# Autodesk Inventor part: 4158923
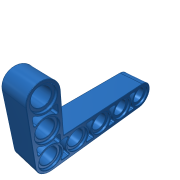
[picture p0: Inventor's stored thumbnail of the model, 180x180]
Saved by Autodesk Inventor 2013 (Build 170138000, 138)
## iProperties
Created: 2013-03
Part Number: 4158923
Material: Generic
Document SubType Name: Modeling
Designer: perblt
Density: 1 g/cm^3
Author: perblt
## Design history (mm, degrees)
sketch "Sketch1"
  geometry: L1 (-1, 2.182)-(1, 2.182); L2 (1, -2.182)-(-1, 2.182); L3 (-1, -2.182)-(1, 2.182); L4 (-2.182, -1)-(-2.182, 1); L5 (2.182, -1)-(-2.182, 1); L6 (-2.182, -1)-(2.182, 1); L7 (2.182, -1)-(1, -1); L8 (-1, -1)-(-2.182, -1); L9 (-1, -2.182)-(-1, -1); L10 (1, 2.182)-(1, 1); L11 (1, -1)-(1, -2.182); L12 (-2.182, 1)-(-1, 1); L13 (1, 1)-(2.182, 1); L14 (-1, 1)-(-1, 2.182); A1 r 2.4 centre (0, 0) between (2.182, -1) and (2.182, 1); A2 r 2.4 centre (0, 0) between (1, 2.182) and (-1, 2.182); A3 r 2.4 centre (0, 0) between (-2.182, 1) and (-2.182, -1); A4 r 2.4 centre (0, 0) between (-1, -2.182) and (1, -2.182); 1 further point
  constraints: 28 end point, 8 parallel, 8 point on circle, 4 centre point, 4 midpoint, 2 horizontal, 2 perpendicular, 1 coincident
  dimensions: "d1" = 2 distance of L1.start L1.end; "d2" = 2 distance of L4.start L4.end
sketch "Sketch2" dims "d10" = 10, "d17" = 10
  geometry: L1 (-12.994, 0)-(44.166, 0) reference; L2 (0, -9.794)-(0, 24.966) reference; L3 (32, -4)-(0, -4); L4 (4, 16)-(4, 4); L5 (4, 4)-(32, 4); L6 (-4, -4)-(-4, -3.79); L7 (-4, 0)-(-4, 16); C1 r 3.2 at (0, 0); C2 r 3.2 at (8, 0); C3 r 3.2 at (16, 0); C4 r 3.2 at (24, 0); C5 r 3.2 at (32, 0); C6 r 3.2 at (0, 8); C7 r 3.2 at (0, 16); A1 r 4 centre (32, 0) between (32, -4) and (32, 4); A2 r 4 centre (0, 16) between (4, 16) and (-4, 16); A3 r 4 centre (0, 0) between (-4, 0) and (0, -4); 1 further point
  constraints: 10 centre point, 10 end point, 6 point on circle, 4 coincident, 4 tangent, 3 parallel, 2 horizontal, 1 vertical, 12 other
  dimensions: "d" = 6.4 diameter of C1; "d7" = 8 distance of C1.centre C2.centre; "d14" = 8 distance of C1.centre C6.centre; "d21" = 8 distance between parallel lines of L4 L7; "d22" = 8 distance between parallel lines of L5 L3; "d23" = 4 radius of A2; "d24" = 4 radius of A1; "d25" = 4 radius of A3
extrude "Extrusion1" new body sketch "Sketch2" stored distance "d26" = 8; taper "d27" = 0 deg
sketch "Sketch3" dims "d34" = 10, "d41" = 10
  geometry: L1 (0, -7.952)-(0, 23.952) reference; L2 (-11.152, 0)-(43.152, 0) reference; C1 r 2.4 at (0, 0); C2 r 3.394 at (0, 0); C3 r 3.394 at (0, 8); C4 r 2.4 at (0, 8); C5 r 3.394 at (0, 16); C6 r 2.4 at (0, 16); C7 r 2.4 at (8, 0); C8 r 3.394 at (8, 0); C9 r 2.4 at (16, 0); C10 r 3.394 at (16, 0); C11 r 2.4 at (24, 0); C12 r 3.394 at (24, 0); C13 r 2.4 at (32, 0); C14 r 3.394 at (32, 0); 1 further point
  constraints: 14 centre point, 8 coincident, 1 horizontal, 1 vertical, 24 other
  dimensions: "d28" = 4.8 diameter of C1; "d31" = 8 distance of C2.centre C3.centre; "d38" = 8 distance of C1.centre C7.centre
extrude "Extrusion2" join sketch "Sketch3" stored distance "d43" = 6.4; taper "d44" = 0 deg
sketch "Sketch4" dims "d60" = 10, "d75" = 10
  geometry: L1 (4, 4)-(32, 4) reference; L2 (32, -4)-(0, -4) reference; L3 (28.83, -3)-(27.17, -3); L4 (27.17, 3)-(28.83, 3); L5 (20.83, -3)-(19.17, -3); L6 (19.17, 3)-(20.83, 3); L7 (12.83, -3)-(11.17, -3); L8 (11.17, 3)-(12.83, 3); L9 (4.83, -3)-(3.17, -3); L10 (3.17, 3)-(4.83, 3); L11 (4, 16)-(4, 4) reference; L12 (-4, 0)-(-4, 16) reference; L13 (3, 3)-(32, 3); L14 (-3, 11.17)-(-3, 12.83); L15 (3, 12.83)-(3, 11.17); L16 (-3, 3.17)-(-3, 4.83); L17 (3, 4.83)-(3, 3.17); C1 r 2.4 at (32, 0) reference; C2 r 2.4 at (24, 0) reference; C3 r 2.4 at (0, 16) reference; C4 r 2.4 at (0, 8) reference; A1 r 3.7 centre (32, 0) between (29.139, 2.346) and (29.139, -2.346); A2 r 3.7 centre (24, 0) between (26.861, -2.346) and (26.861, 2.346); A3 r 0.4 centre (27.17, -2.6) between (26.861, -2.346) and (27.17, -3); A4 r 0.4 centre (28.83, -2.6) between (28.83, -3) and (29.139, -2.346); A5 r 0.4 centre (27.17, 2.6) between (27.17, 3) and (26.861, 2.346); A6 r 0.4 centre (28.83, 2.6) between (29.139, 2.346) and (28.83, 3); A7 r 0.4 centre (20.83, -2.6) between (20.83, -3) and (21.139, -2.346); A8 r 0.4 centre (19.17, -2.6) between (18.861, -2.346) and (19.17, -3); A9 r 3.7 centre (24, 0) between (21.139, 2.346) and (21.139, -2.346); A10 r 3.7 centre (16, 0) between (18.861, -2.346) and (18.861, 2.346); A11 r 0.4 centre (20.83, 2.6) between (21.139, 2.346) and (20.83, 3); A12 r 0.4 centre (19.17, 2.6) between (19.17, 3) and (18.861, 2.346); A13 r 0.4 centre (12.83, -2.6) between (12.83, -3) and (13.139, -2.346); A14 r 0.4 centre (11.17, -2.6) between (10.861, -2.346) and (11.17, -3); A15 r 3.7 centre (16, 0) between (13.139, 2.346) and (13.139, -2.346); A16 r 3.7 centre (8, 0) between (10.861, -2.346) and (10.861, 2.346); A17 r 0.4 centre (12.83, 2.6) between (13.139, 2.346) and (12.83, 3); A18 r 0.4 centre (11.17, 2.6) between (11.17, 3) and (10.861, 2.346); A19 r 0.4 centre (4.83, -2.6) between (4.83, -3) and (5.139, -2.346); A20 r 0.4 centre (3.17, -2.6) between (2.861, -2.346) and (3.17, -3); A21 r 3.7 centre (8, 0) between (5.139, 2.346) and (5.139, -2.346); A22 r 3.7 centre (0, 0) between (2.861, -2.346) and (2.861, 2.346); A23 r 0.4 centre (4.83, 2.6) between (5.139, 2.346) and (4.83, 3); A24 r 0.4 centre (3.17, 2.6) between (3.17, 3) and (2.861, 2.346); A25 r 3.7 centre (0, 16) between (-2.346, 13.139) and (2.346, 13.139); A26 r 0.4 centre (-2.6, 12.83) between (-2.346, 13.139) and (-3, 12.83); A27 r 0.4 centre (-2.6, 11.17) between (-3, 11.17) and (-2.346, 10.861); A28 r 0.4 centre (2.6, 11.17) between (2.346, 10.861) and (3, 11.17); A29 r 0.4 centre (2.6, 12.83) between (3, 12.83) and (2.346, 13.139); A30 r 3.7 centre (0, 8) between (2.346, 10.861) and (-2.346, 10.861); A31 r 0.4 centre (-2.6, 3.17) between (-3, 3.17) and (-2.346, 2.861); A32 r 0.4 centre (2.6, 3.17) between (2.346, 2.861) and (3, 3.17); A33 r 3.7 centre (0, 8) between (-2.346, 5.139) and (2.346, 5.139); A34 r 0.4 centre (-2.6, 4.83) between (-2.346, 5.139) and (-3, 4.83); A35 r 0.4 centre (2.6, 4.83) between (3, 4.83) and (2.346, 5.139); A36 r 3.7 centre (0, 0) between (2.346, 2.861) and (-2.346, 2.861); 1 further point
  constraints: 72 point on circle, 36 centre point, 26 end point, 14 tangent, 4 coincident, 3 parallel, 1 horizontal, 1 vertical, 88 other
  dimensions: "d45" = 7.4 diameter of A1; "d46" = 7.4 diameter of A2; "d49" = 0.8 diameter of A3; "d50" = 0.8 diameter of A4; "d51" = 0.8 diameter of A5; "d52" = 0.8 diameter of A6; "d57" = 8 distance of A1.end A7.end; "d62" = 7.4 diameter of A25; "d66" = 0.8 diameter of A26; "d67" = 0.8 diameter of A27; "d68" = 0.8 diameter of A28; "d69" = 0.8 diameter of A29; "d72" = 8 distance of L15.start L17.start
extrude "Extrusion3" cut sketch "Sketch4" stored distance "d53" = 10; taper "d54" = 0 deg
sketch "Sketch5" dims "d82" = 10
  geometry: L1 (26.635, 3.313)-(29.368, 3.313); L2 (29.368, 3.313)-(29.368, -3.607); L3 (29.368, -3.607)-(26.635, -3.607); L4 (26.635, -3.607)-(26.635, 3.313); L5 (4, 4)-(32, 4) reference; L6 (4, 16)-(4, 4) reference; L7 (18.635, 3.313)-(21.368, 3.313); L8 (21.368, 3.313)-(21.368, -3.607); L9 (21.368, -3.607)-(18.635, -3.607); L10 (18.635, -3.607)-(18.635, 3.313); L11 (10.635, 3.313)-(13.368, 3.313); L12 (13.368, 3.313)-(13.368, -3.607); L13 (13.368, -3.607)-(10.635, -3.607); L14 (10.635, -3.607)-(10.635, 3.313); L15 (2.635, 3.313)-(5.368, 3.313); L16 (5.368, 3.313)-(5.368, -3.607); L17 (5.368, -3.607)-(2.635, -3.607); L18 (2.635, -3.607)-(2.635, 3.313); L19 (3.222, 10.513)-(-3.426, 10.513); L20 (-3.426, 10.513)-(-3.426, 13.403); L21 (-3.426, 13.403)-(3.222, 13.403); L22 (3.222, 13.403)-(3.222, 10.513); L23 (-3.137, 5.371)-(3.222, 5.371); L24 (3.222, 5.371)-(3.222, 3.313); L25 (2.635, 2.582)-(-3.137, 2.582); L26 (-3.137, 2.582)-(-3.137, 5.371); 1 further point
  constraints: 48 end point, 6 parallel, 4 horizontal, 3 perpendicular, 2 point on line, 24 other
  dimensions: "d79" = 8 distance of L1.start L7.start
extrude "Extrusion4" join sketch "Sketch5" stored distance "d84" = 1.6; taper "d85" = 0 deg
sketch "Sketch6"
  geometry: L1 (-3, 3.17)-(-3, 4.83) reference; L2 (3, 4.83)-(3, 3.17) reference; L3 (3.17, 3)-(4.83, 3) reference; L4 (4.83, -3)-(3.17, -3) reference; L5 (2.973, 2.202)-(2.45, 2.159); L6 (2.45, 2.159)-(2, 2.735); L7 (2, 2.735)-(2.202, 2.973); L8 (3, 3.375)-(3.375, 3.568); L9 (3.375, 3.568)-(3.375, 3); A1 r 0.4 centre (-2.6, 3.17) between (-3, 3.17) and (-2.346, 2.861) reference; A2 r 3.7 centre (0, 0) between (2.346, 2.861) and (-2.346, 2.861) reference; A3 r 0.4 centre (2.6, 3.17) between (2.346, 2.861) and (3, 3.17) reference; A4 r 0.4 centre (2.6, 4.83) between (3, 4.83) and (2.346, 5.139) reference; A5 r 3.7 centre (0, 8) between (-2.346, 5.139) and (2.346, 5.139) reference; A6 r 0.4 centre (-2.6, 4.83) between (-2.346, 5.139) and (-3, 4.83) reference; A7 r 0.4 centre (3.17, 2.6) between (3.17, 3) and (2.861, 2.346) reference; A8 r 3.7 centre (0, 0) between (2.861, -2.346) and (2.861, 2.346) reference; A9 r 0.4 centre (3.17, -2.6) between (2.861, -2.346) and (3.17, -3) reference; A10 r 0.4 centre (4.83, -2.6) between (4.83, -3) and (5.139, -2.346) reference; A11 r 3.7 centre (8, 0) between (5.139, 2.346) and (5.139, -2.346) reference; A12 r 0.4 centre (4.83, 2.6) between (5.139, 2.346) and (4.83, 3) reference; A13 r 0.5 centre (3.375, 2.5) between (3.375, 3) and (2.973, 2.202); A14 r 0.5 centre (2.5, 3.375) between (2.202, 2.973) and (3, 3.375); 1 further point
  constraints: 10 end point, 6 point on circle, 4 tangent, 2 centre point, 2 point on line
  dimensions: "d86" = 1 diameter of A13; "d87" = 1 diameter of A14
extrude "Extrusion5" join sketch "Sketch6" stored distance "d88" = 8; taper "d89" = 0 deg
fillet "Fillet1" dims "d90" = 0.1, "d91" = 0.1
body "Solid1"
node "Projected Loop1"
node "Projected Loop2"
other parameters: "d0" = 4.8, "d47" = 1, "d48" = 1, "d63" = 7.4, "d64" = 1, "d65" = 1
